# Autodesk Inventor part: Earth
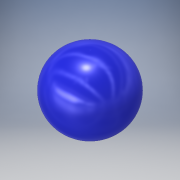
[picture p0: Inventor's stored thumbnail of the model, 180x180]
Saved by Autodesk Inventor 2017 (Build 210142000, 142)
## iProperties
Created: 2016-07
Part Number: Earth
Material: ABS Plastic
Document SubType Name: Modeling
Designer: Stan
Density: 1.06 g/cm^3
Appearance: Blue - Wall Paint - Glossy
Author: Stan
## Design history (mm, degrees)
sketch "Sketch1"
  geometry: L1 (-2.117, -12.522)-(1.058, -12.522); L2 (1.058, -12.522)-(1.058, 12.656); A1 r 12.7 centre (0, 0) between (1.058, 12.656) and (-2.117, -12.522); 1 further point
  constraints: 4 end point, 2 point on circle, 1 centre point, 1 coincident, 1 horizontal, 1 perpendicular
  dimensions: "d0" = 25.4 diameter of A1; "d2" = 3.175 distance of L1.start L1.end
revolve "Revolution1" sketch "Sketch1" stored, may be unused: angle "d3" = 90 deg
sketch "Sketch3"
  geometry: C1 r 3.175 at (0, 0) reference; C2 r 1.587 at (0, 0); 1 further point
  constraints: 1 centre point, 1 coincident
  dimensions: "d7" = 3.175 diameter of C2
extrude "Extrusion2" cut sketch "Sketch3" distance "d8" = 7.62; taper "d9" = 0 deg
body "Solid1"
